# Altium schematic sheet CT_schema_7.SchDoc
size 296 x 239 mm
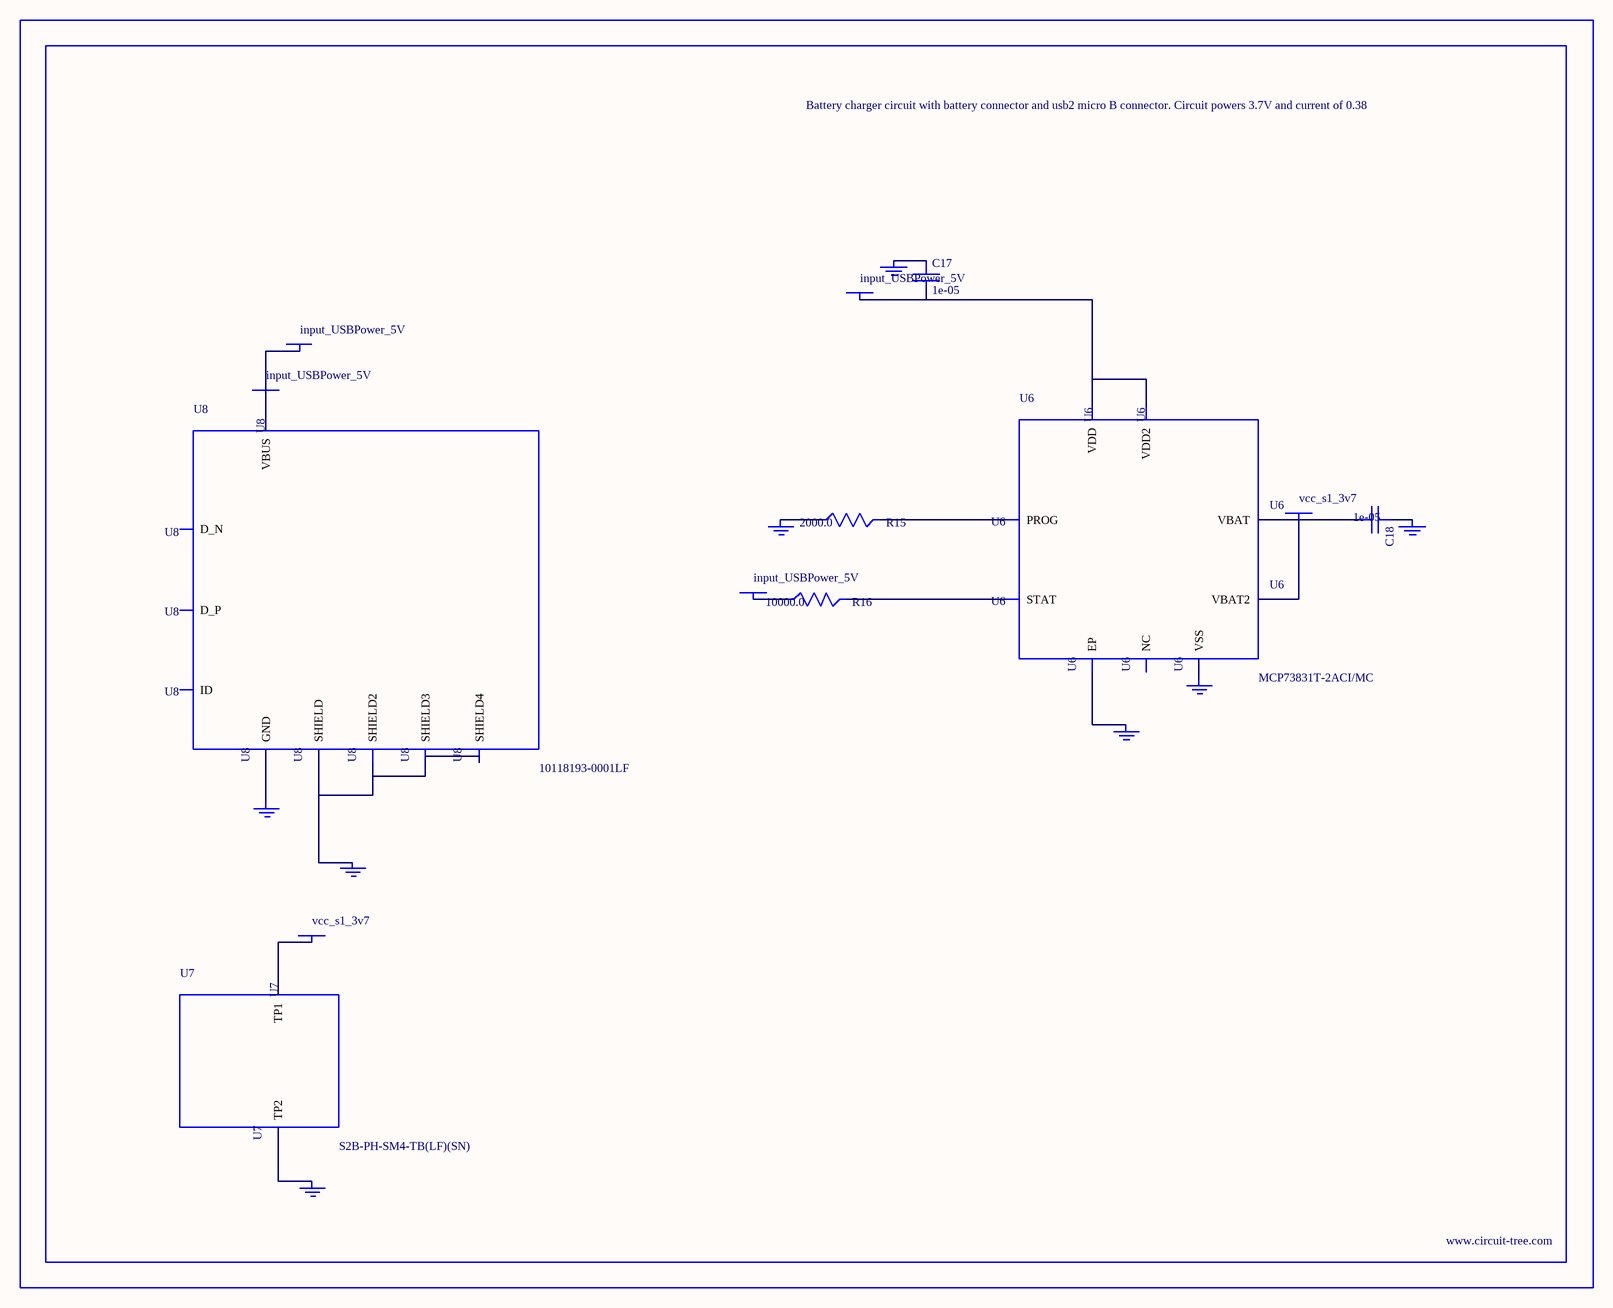
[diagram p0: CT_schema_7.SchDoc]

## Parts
BORDER6  (no value)
C17  1e-05  [C1206]
C18  1e-05  [C1206]
GND_INSTANCE_6_0  (no value)
GND_INSTANCE_6_1  (no value)
GND_INSTANCE_6_2  (no value)
GND_INSTANCE_6_3  (no value)
GND_INSTANCE_6_4  (no value)
GND_INSTANCE_6_5  (no value)
GND_INSTANCE_6_6  (no value)
GND_INSTANCE_6_7  (no value)
POWER_INSTANCE_6_0  input_USBPower_5V
POWER_INSTANCE_6_1  input_USBPower_5V
POWER_INSTANCE_6_2  vcc_s1_3v7
POWER_INSTANCE_6_3  vcc_s1_3v7
POWER_INSTANCE_6_4  input_USBPower_5V
POWER_INSTANCE_6_5  input_USBPower_5V
R15  2000.0  [R0603]
R16  10000.0  [R0603]
U6  MCP73831T-2ACI/MC  [DFN8_2X3MC]
U7  S2B-PH-SM4-TB(LF)(SN)  [JST-2-SMD]
U8  10118193-0001LF  [FCI_10118193-0001LF]

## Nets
NetC17_1: C17.1 GND_INSTANCE_6_0.0(GND)
NetC17_2: C17.2 POWER_INSTANCE_6_0.0(PWR) U6.1(VDD) U6.2(VDD2)
NetC18_1: C18.1 GND_INSTANCE_6_1.0(GND)
NetC18_2: C18.2 POWER_INSTANCE_6_2.0(PWR) U6.3(VBAT) U6.4(VBAT2)
NetGND_INSTANCE_6_2_0: GND_INSTANCE_6_2.0(GND) R15.1
NetGND_INSTANCE_6_3_0: GND_INSTANCE_6_3.0(GND) U6.9(EP)
NetGND_INSTANCE_6_4_0: GND_INSTANCE_6_4.0(GND) U6.6(VSS)
NetGND_INSTANCE_6_5_0: GND_INSTANCE_6_5.0(GND) U7.2(TP2)
NetGND_INSTANCE_6_6_0: GND_INSTANCE_6_6.0(GND) U8.6(SHIELD) U8.7(SHIELD2) U8.8(SHIELD3) U8.9(SHIELD4)
NetGND_INSTANCE_6_7_0: GND_INSTANCE_6_7.0(GND) U8.5(GND)
NetPOWER_INSTANCE_6_1_0: POWER_INSTANCE_6_1.0(PWR) R16.1
NetPOWER_INSTANCE_6_3_0: POWER_INSTANCE_6_3.0(PWR) U7.1(TP1)
NetPOWER_INSTANCE_6_4_0: POWER_INSTANCE_6_4.0(PWR) POWER_INSTANCE_6_5.0(PWR) U8.1(VBUS)
NetR15_2: R15.2 U6.8(PROG)
NetR16_2: R16.2 U6.5(STAT)

Not connected (* = marked no-connect by the designer): U6 7(NC); U8 2(D_N) 3(D_P) 4(ID)

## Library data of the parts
BORDER6 = BORDER_PAGE6
C17 C18 = C1206C106K3RACTU
GND_INSTANCE_6_0-GND_INSTANCE_6_7 = GND
POWER_INSTANCE_6_0-POWER_INSTANCE_6_5 = PWR
R15 = RC0603JR-072KL
R16 = RC0603JR-0710KL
